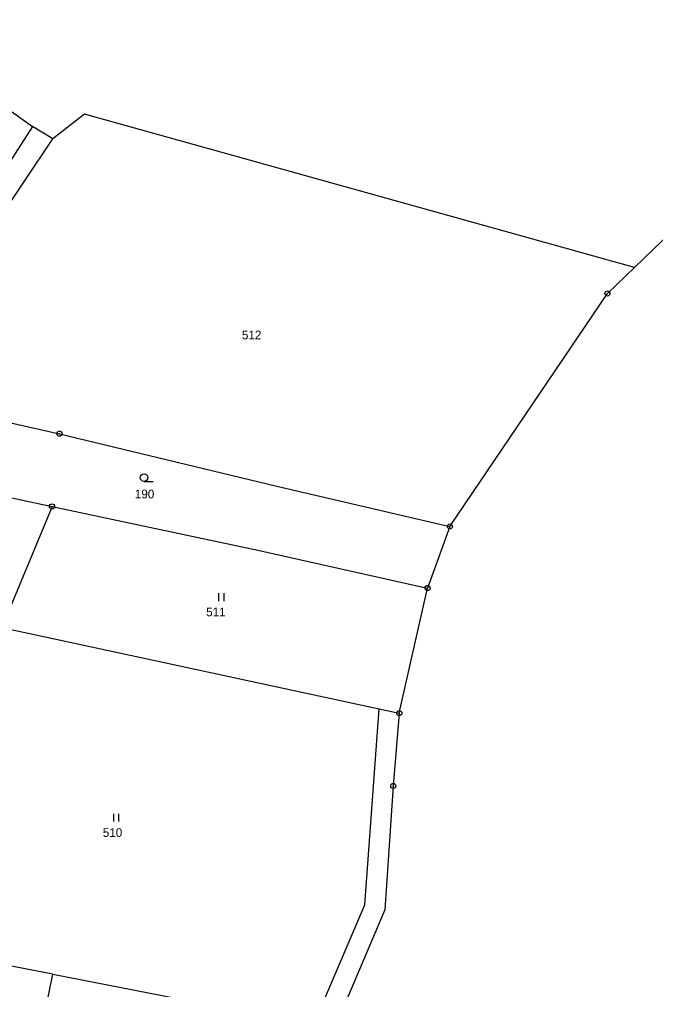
# Model space of a CAD drawing. Extents: x -719614 to -717765, y -1095834 to -1093862.
# Drawn here: x -718673.7 to -718549.9, y -1095371.4 to -1095182.6 of the extents above; entities that cross this region are included whole.
import ezdxf
from ezdxf.enums import TextEntityAlignment as Align

# ---------------------------------------------------------------- set-up
doc = ezdxf.new("R2010")
doc.units = 0
doc.header["$LTSCALE"] = 0.68
for name, color, linetype, lineweight in [('1', 7, 'Continuous', 25), ('3', 7, 'Continuous', 25), ('8', 7, 'Continuous', 25)]:
    doc.layers.add(name, color=color, linetype=linetype, lineweight=lineweight)
doc.layers.add('2', color=7, linetype='Continuous')

msp = doc.modelspace()

# ---------------------------------------------------------------- linework, layer by layer
at = {"layer": '1'}
for p, q in [((-718700.4, -1095182.55), (-718671.13, -1095203.4)), ((-718661.04, -1095201), (-718667.2, -1095205.81)), ((-718554, -1095230.84), (-718661.04, -1095201)), ((-718671.13, -1095203.4), (-718683.65, -1095222.53)), ((-718667.2, -1095205.81), (-718671.13, -1095203.4)), ((-718693.53, -1095244.95), (-718667.2, -1095205.81)), ((-718546.92, -1095224.03), (-718554, -1095230.84)), ((-718559.26, -1095235.9), (-718554, -1095230.84)), ((-718589.9, -1095281.26), (-718559.26, -1095235.9)), ((-718702.39, -1095255.04), (-718665.9, -1095263.19)), ((-718665.9, -1095263.19), (-718623.58, -1095273.41)), ((-718682.09, -1095274.23), (-718667.35, -1095277.34)), ((-718623.58, -1095273.41), (-718589.9, -1095281.26)), ((-718667.35, -1095277.34), (-718677.11, -1095300.91)), ((-718667.35, -1095277.34), (-718627.28, -1095285.88)), ((-718589.9, -1095281.26), (-718594.25, -1095293.23)), ((-718627.28, -1095285.88), (-718594.25, -1095293.23)), ((-718599.76, -1095317.59), (-718594.25, -1095293.23)), ((-718677.11, -1095300.91), (-718603.71, -1095316.74)), ((-718606.5, -1095354.9), (-718603.71, -1095316.74)), ((-718603.71, -1095316.74), (-718599.76, -1095317.59)), ((-718599.76, -1095317.59), (-718600.93, -1095331.76)), ((-718600.93, -1095331.76), (-718602.56, -1095355.86)), ((-718614.65, -1095374.04), (-718606.5, -1095354.9)), ((-718602.56, -1095355.86), (-718611.04, -1095375.76)), ((-718667.2, -1095368.41), (-718709.73, -1095360.26)), ((-718669.47, -1095379.53), (-718667.2, -1095368.41)), ((-718667.2, -1095368.41), (-718616.65, -1095378.21))]:
    msp.add_line(p, q, dxfattribs=at)
at = {"layer": '3'}
for p, q in [((-718649.433, -1095272.48), (-718647.683, -1095272.48)), ((-718634.861, -1095295.76), (-718634.861, -1095294.26)), ((-718633.86, -1095295.76), (-718633.86, -1095294.26)), ((-718655.321, -1095338.7), (-718655.321, -1095337.2)), ((-718654.32, -1095338.7), (-718654.32, -1095337.2))]:
    msp.add_line(p, q, dxfattribs=at)
msp.add_circle((-718649.4329, -1095271.7298), 0.75, dxfattribs=at)
at = {"layer": '8'}
for centre, radius in [((-718559.26, -1095235.8999), 0.5), ((-718559.26, -1095235.8999), 0.0303), ((-718665.9, -1095263.1899), 0.5), ((-718665.9, -1095263.1899), 0.0303), ((-718667.35, -1095277.3399), 0.5), ((-718667.35, -1095277.3399), 0.0303), ((-718589.9, -1095281.2599), 0.5), ((-718589.9, -1095281.2599), 0.0303), ((-718594.25, -1095293.2299), 0.5), ((-718594.25, -1095293.2299), 0.0303), ((-718599.76, -1095317.5899), 0.5), ((-718599.76, -1095317.5899), 0.0303), ((-718600.93, -1095331.7599), 0.5), ((-718600.93, -1095331.7599), 0.0303)]:
    msp.add_circle(centre, radius, dxfattribs=at)

# ---------------------------------------------------------------- texts
at = {"layer": '2'}
for s, p in [('512', (-718628.499, -1095244.822)), ('190', (-718649.339, -1095275.775)), ('511', (-718635.449, -1095298.742)), ('510', (-718655.579, -1095341.682))]:
    msp.add_text(s, height=1.7, dxfattribs=at).set_placement(p, align=Align.CENTER)

doc.saveas('drawing.dxf')
